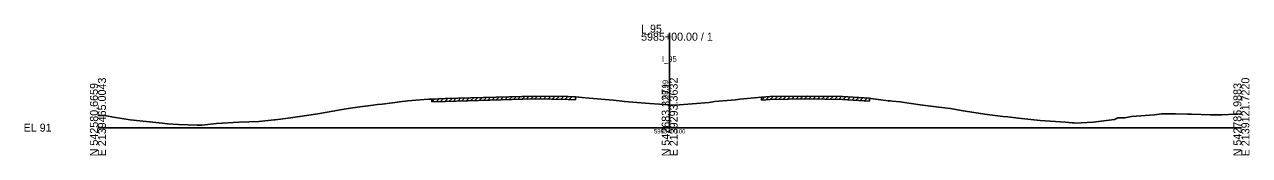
# Model space of a CAD drawing. Extents: x -12534 to 3403, y -1332 to 21983.
# Drawn here: x -25.7 to 402.8, y 15990.3 to 16036 of the extents above; entities that cross this region are included whole.
import ezdxf

# ---------------------------------------------------------------- set-up
doc = ezdxf.new("R2010")
doc.units = 0
for name, color, linetype in [('RD_GPK_XS_Cell', 7, 'Continuous'), ('RD_XS_ExGround', 7, 'Continuous'), ('RD_XS_ExPaveRet', 7, 'Continuous'), ('RD_XS_TX_Baseline', 7, 'Continuous'), ('RD_XS_TX_Elev_EX', 7, 'Continuous'), ('RD_XS_TX_Station', 7, 'Continuous')]:
    doc.layers.add(name, color=color, linetype=linetype)

msp = doc.modelspace()

# ---------------------------------------------------------------- linework, layer by layer
at = {"layer": 'RD_GPK_XS_Cell'}
for p, q in [((200, 16000), (200, 16033.17)), ((0, 16000), (200, 16000)), ((200, 16000), (400, 16000))]:
    msp.add_line(p, q, dxfattribs=at)
at = {"layer": 'RD_XS_ExGround'}
msp.add_lwpolyline([(0, 16004.24), (2.95, 16004.09), (5.41, 16003.68), (11.22, 16002.78), (22.51, 16001.54), (24.34, 16001.29), (28.15, 16001.15), (34.72, 16000.89), (35.57, 16000.91), (36.37, 16000.91), (41.47, 16001.51), (49.28, 16001.92), (56.34, 16002.19), (61.61, 16002.7), (62.03, 16002.74), (66.54, 16003.38), (69.78, 16003.84), (76.91, 16004.88), (85.49, 16006.38), (87.54, 16006.73), (91.58, 16007.27), (96.28, 16007.86), (97.82, 16008.08), (99.42, 16008.26), (104.79, 16008.91), (105.49, 16009.01), (108.36, 16009.33), (112.62, 16009.69), (115.74, 16009.93), (116.84, 16010.01), (121.49, 16010.19), (152.66, 16011.02), (164.51, 16010.86), (167.03, 16010.77), (169.4, 16010.54), (171.83, 16010.31), (180.21, 16009.58), (182.38, 16009.39), (183.37, 16009.28), (184.15, 16009.19), (191.45, 16008.54), (192.96, 16008.41), (200, 16007.99), (201.96, 16007.87), (213.77, 16008.83), (214.44, 16008.89), (215.2, 16009.06), (215.71, 16009.09), (223.04, 16009.78), (224.59, 16009.94), (229.65, 16010.42), (232.17, 16010.64), (235.13, 16010.88), (248.1, 16011.06), (260.47, 16010.84), (269.9, 16010.28), (270.39, 16010.17), (276.39, 16009.42), (277.09, 16009.33), (277.87, 16009.24), (280.75, 16009), (281.33, 16008.92), (284.45, 16008.49), (287.62, 16008.04), (294.19, 16007.2), (298.23, 16006.69), (302, 16006.05), (308.76, 16004.92), (311.07, 16004.6), (316.58, 16003.86), (318.29, 16003.74), (321.98, 16003.34), (329.64, 16002.47), (338.49, 16001.93), (340.79, 16001.73), (341.32, 16001.72), (341.9, 16001.58), (348.14, 16001.9), (355.62, 16002.84), (356.6, 16003.29), (356.76, 16003.5), (359.2, 16003.43), (361.53, 16003.93), (369.63, 16004.51), (372.09, 16004.86), (373.31, 16004.8), (376.99, 16004.8), (381.17, 16004.73), (382.57, 16004.73), (389.14, 16004.54), (393.16, 16004.52), (400, 16004.85)], dxfattribs=at)
at = {"layer": 'RD_XS_ExPaveRet'}
for p, q in [((116.84, 16009.01), (117.88, 16010.05)), ((116.84, 16009.01), (116.84, 16010.01)), ((118.34, 16009.06), (119.38, 16010.11)), ((119.84, 16009.12), (120.88, 16010.16)), ((121.34, 16009.18), (122.37, 16010.21)), ((121.49, 16009.19), (152.66, 16010.02)), ((122.84, 16009.22), (123.87, 16010.25)), ((124.34, 16009.26), (125.37, 16010.29)), ((125.84, 16009.3), (126.87, 16010.33)), ((127.34, 16009.35), (128.37, 16010.37)), ((128.84, 16009.39), (129.87, 16010.41)), ((130.34, 16009.43), (131.37, 16010.45)), ((131.84, 16009.47), (132.87, 16010.49)), ((133.34, 16009.51), (134.37, 16010.53)), ((134.84, 16009.55), (135.87, 16010.57)), ((136.34, 16009.59), (137.37, 16010.61)), ((137.84, 16009.63), (138.87, 16010.65)), ((139.34, 16009.67), (140.37, 16010.69)), ((140.84, 16009.71), (141.87, 16010.74)), ((142.34, 16009.75), (143.37, 16010.78)), ((143.84, 16009.79), (144.87, 16010.82)), ((145.34, 16009.83), (146.37, 16010.86)), ((146.84, 16009.87), (147.87, 16010.9)), ((148.34, 16009.91), (149.37, 16010.94)), ((149.84, 16009.95), (150.87, 16010.98)), ((151.34, 16009.99), (152.37, 16011.02)), ((152.66, 16010.02), (164.51, 16009.86)), ((152.84, 16010.02), (153.82, 16011.01)), ((154.34, 16010), (155.32, 16010.99)), ((155.84, 16009.98), (156.82, 16010.97)), ((157.34, 16009.96), (158.32, 16010.95)), ((158.84, 16009.94), (159.82, 16010.93)), ((160.34, 16009.92), (161.32, 16010.91)), ((161.84, 16009.9), (162.82, 16010.89)), ((163.34, 16009.88), (164.32, 16010.87)), ((164.84, 16009.85), (165.8, 16010.81)), ((167.03, 16010.77), (167.03, 16009.77)), ((232.17, 16009.64), (233.26, 16010.73)), ((232.17, 16009.64), (232.17, 16010.64)), ((233.67, 16009.76), (234.76, 16010.85)), ((235.13, 16009.88), (248.1, 16010.06)), ((235.17, 16009.88), (236.19, 16010.89)), ((236.67, 16009.9), (237.69, 16010.91)), ((238.17, 16009.92), (239.19, 16010.93)), ((239.67, 16009.94), (240.69, 16010.95)), ((241.17, 16009.96), (242.19, 16010.98)), ((242.67, 16009.98), (243.69, 16011)), ((244.17, 16010), (245.19, 16011.02)), ((245.67, 16010.02), (246.69, 16011.04)), ((247.17, 16010.05), (248.19, 16011.06)), ((248.1, 16010.06), (260.47, 16009.84)), ((248.67, 16010.05), (249.66, 16011.03)), ((250.17, 16010.02), (251.16, 16011)), ((251.67, 16009.99), (252.66, 16010.98)), ((253.17, 16009.97), (254.16, 16010.95)), ((254.67, 16009.94), (255.66, 16010.92)), ((256.17, 16009.91), (257.16, 16010.9)), ((257.67, 16009.89), (258.66, 16010.87)), ((259.17, 16009.86), (260.16, 16010.84)), ((260.67, 16009.82), (261.62, 16010.77)), ((262.17, 16009.74), (263.12, 16010.68)), ((263.67, 16009.65), (264.62, 16010.59)), ((265.17, 16009.56), (266.12, 16010.5)), ((266.67, 16009.47), (267.62, 16010.41)), ((268.17, 16009.38), (269.12, 16010.32)), ((269.9, 16010.28), (269.9, 16009.28)), ((116.84, 16009.01), (121.49, 16009.19)), ((164.51, 16009.86), (167.03, 16009.77)), ((232.17, 16009.64), (235.13, 16009.88)), ((260.47, 16009.84), (269.9, 16009.28))]:
    msp.add_line(p, q, dxfattribs=at)

# ---------------------------------------------------------------- texts
at = {"layer": 'RD_GPK_XS_Cell'}
for s, p in [('I_95', (190, 16033.17)), ('5985+00.00 / 1', (190, 16030.37)), ('EL 91', (-26, 15998.6))]:
    msp.add_text(s, height=2.8, dxfattribs=at).set_placement(p)
for s, p in [('N 542580.6659', (0, 15990)), ('E 2139465.0043', (2.8, 15990)), ('N 542683.3271', (200, 15990)), ('E 2139293.3632', (202.8, 15990)), ('N 542785.9883', (400, 15990)), ('E 2139121.7220', (402.8, 15990))]:
    msp.add_text(s, height=2.8, rotation=90, dxfattribs=at).set_placement(p)
at = {"layer": 'RD_XS_TX_Baseline'}
msp.add_text('I_95', height=2, dxfattribs=at).set_placement((197.28, 16022.99))
at = {"layer": 'RD_XS_TX_Elev_EX'}
msp.add_text('98.99', height=2, rotation=90, dxfattribs=at).set_placement((199.5, 16009.99))
at = {"layer": 'RD_XS_TX_Station'}
msp.add_text('5985+00.00', height=1.5, dxfattribs=at).set_placement((194.51, 15997.99))

doc.saveas('drawing.dxf')
